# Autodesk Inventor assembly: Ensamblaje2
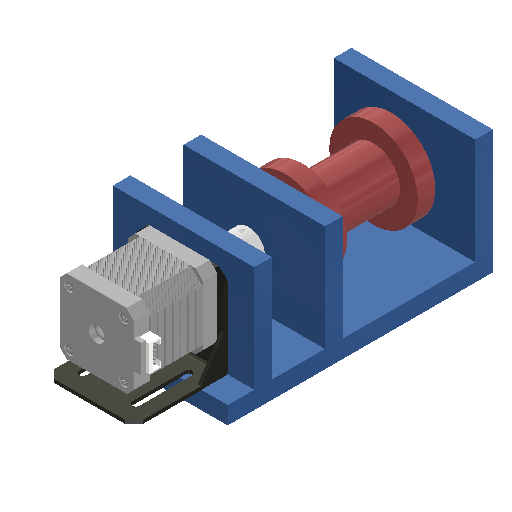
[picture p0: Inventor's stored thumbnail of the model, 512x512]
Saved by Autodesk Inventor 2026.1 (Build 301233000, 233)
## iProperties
Created: 2025-06
Part Number: Ensamblaje2
Document SubType Name: Assembly
Designer: piero
Author: piero
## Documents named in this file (11)
- D:\Tesis\Modelo 3D\CAD\Ensamblaje2.iam
- D:\Tesis\Modelo 3D\CAD\soporte_inferior.ipt
- D:\Tesis\Modelo 3D\CAD\carrete.ipt
- D:\Tesis\Modelo 3D\CAD\acople_suave.ipt
- D:\Tesis\Modelo 3D\CAD\Stepper Motor Nema 17_.ipt
- D:\Tesis\Modelo 3D\CAD\perno_pasante.ipt
- D:\Tesis\Modelo 3D\CAD\Soporte_NEMA17.ipt
- C:\Users\piero\OneDrive\Documentos\Inventor\Content Center Files\R2026\es-ES\BS EN ISO 7046-2 H\BS EN ISO 7046-2 H - M3x20 - 8.8 - H1.ipt
- C:\Users\piero\OneDrive\Documentos\UTEC\Ciclo 2025-1\PFC_1\ModeloBase\Roda-608\w_608-2rs1.iam
- D:\Tesis\Modelo 3D\CAD\Brida1.ipt
- C:\Users\piero\OneDrive\Documentos\Inventor\Content Center Files\R2026\es-ES\AS 1421(4)\AS 1421 - M3 x 4 Punta plana.ipt
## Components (23 placed, 10 different names)
1. soporte_inferior:1 — Coincidencia:5, Coincidencia:8, De rotación:1
2. carrete:1 — Coincidencia:7, Coincidencia:17, Coincidencia:18, Coincidencia:19, Coincidencia:20, Coincidencia:21, Coincidencia:22
3. acople_suave:2 — Coincidencia:6, Coincidencia:16
4. Stepper Motor Nema 17_:2 — Coincidencia:8
5. perno_pasante:1 — Coincidencia:5, Coincidencia:6, Coincidencia:7, Coincidencia:13, Coincidencia:14, Coincidencia:15
6. Soporte_NEMA17:1
7. BS EN ISO 7046-2 H M3x20 - 8.8 - H1:1
8. BS EN ISO 7046-2 H M3x20 - 8.8 - H1:2
9. BS EN ISO 7046-2 H M3x20 - 8.8 - H1:3
10. BS EN ISO 7046-2 H M3x20 - 8.8 - H1:4
11. w_608-2rs1:1 [sub-assembly] — Coincidencia:13, De rotación:1
12. Brida1:1 — Coincidencia:14
13. Brida1:2 — Coincidencia:15
14. AS 1421 Punta plana - Métrico M3 x 4 Punta plana:1
15. AS 1421 Punta plana - Métrico M3 x 4 Punta plana:3
16. AS 1421 Punta plana - Métrico M3 x 4 Punta plana:4
17. AS 1421 Punta plana - Métrico M3 x 4 Punta plana:5 — Coincidencia:16
18. AS 1421 Punta plana - Métrico M3 x 4 Punta plana:6 — Coincidencia:18
19. AS 1421 Punta plana - Métrico M3 x 4 Punta plana:7 — Coincidencia:19
20. AS 1421 Punta plana - Métrico M3 x 4 Punta plana:8 — Coincidencia:17
21. AS 1421 Punta plana - Métrico M3 x 4 Punta plana:9 — Coincidencia:21
22. AS 1421 Punta plana - Métrico M3 x 4 Punta plana:10 — Coincidencia:20
23. AS 1421 Punta plana - Métrico M3 x 4 Punta plana:11 — Coincidencia:22
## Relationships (15: Mate 14, RevoluteJoint 1)
- Coincidencia:5 [Mate]: soporte_inferior:1 ↔ perno_pasante:1
- Coincidencia:6 [Mate]: acople_suave:2 ↔ perno_pasante:1
- Coincidencia:7 [Mate]: carrete:1 ↔ perno_pasante:1
- Coincidencia:8 [Mate]: soporte_inferior:1 ↔ Stepper Motor Nema 17_:2
- Coincidencia:13 [Mate]: perno_pasante:1 ↔ w_608-2rs1:1
- Coincidencia:14 [Mate]: perno_pasante:1 ↔ Brida1:1
- Coincidencia:15 [Mate]: perno_pasante:1 ↔ Brida1:2
- De rotación:1 [RevoluteJoint]: soporte_inferior:1 ↔ w_608-2rs1:1
- Coincidencia:16 [Mate]: acople_suave:2 ↔ AS 1421 Punta plana - Métrico M3 x 4 Punta plana:5
- Coincidencia:17 [Mate]: carrete:1 ↔ AS 1421 Punta plana - Métrico M3 x 4 Punta plana:8
- Coincidencia:18 [Mate]: carrete:1 ↔ AS 1421 Punta plana - Métrico M3 x 4 Punta plana:6
- Coincidencia:19 [Mate]: carrete:1 ↔ AS 1421 Punta plana - Métrico M3 x 4 Punta plana:7
- Coincidencia:20 [Mate]: carrete:1 ↔ AS 1421 Punta plana - Métrico M3 x 4 Punta plana:10
- Coincidencia:21 [Mate]: carrete:1 ↔ AS 1421 Punta plana - Métrico M3 x 4 Punta plana:9
- Coincidencia:22 [Mate]: carrete:1 ↔ AS 1421 Punta plana - Métrico M3 x 4 Punta plana:11
